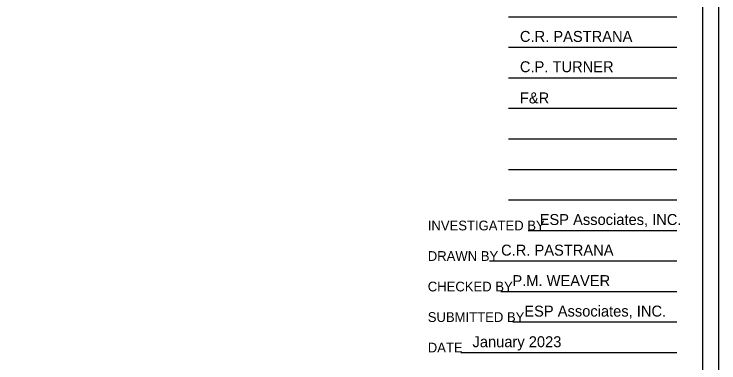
# Model space of a CAD drawing. Extents: x 265553 to 275568, y 168312 to 173522.
# Drawn here: x 267932 to 268472, y 172522 to 172789 of the extents above; entities that cross this region are included whole.
import ezdxf

# ---------------------------------------------------------------- set-up
doc = ezdxf.new("R2010")
doc.units = 0
doc.layers.add('Geotech Sheets and Borders Cell', color=7, linetype='Continuous')
doc.layers.add('Sheet Plot Border Inside CELL', color=7, linetype='Continuous')

msp = doc.modelspace()

# ---------------------------------------------------------------- linework, layer by layer
at = {"layer": 'Geotech Sheets and Borders Cell'}
for p, q in [((268310.32, 172787.01), (268439.27, 172787.01)), ((268310.32, 172763.61), (268439.27, 172763.61)), ((268310.32, 172740.21), (268439.27, 172740.21)), ((268310.32, 172716.81), (268439.27, 172716.81)), ((268310.32, 172693.41), (268439.27, 172693.41)), ((268310.32, 172670.01), (268439.27, 172670.01)), ((268310.32, 172646.61), (268439.27, 172646.61)), ((268325.43, 172623.21), (268439.27, 172623.21)), ((268295.9, 172599.81), (268439.27, 172599.81)), ((268304.56, 172576.41), (268439.27, 172576.41)), ((268313.67, 172553.01), (268439.27, 172553.01)), ((268274.01, 172529.61), (268439.27, 172529.61))]:
    msp.add_line(p, q, dxfattribs=at)
msp.add_lwpolyline([(266959.02, 173192.58), (268459.02, 173192.58), (268459.02, 172142.58), (266959.02, 172142.58)], close=True, dxfattribs=at)
at = {"layer": 'Sheet Plot Border Inside CELL'}
msp.add_lwpolyline([(266803.85, 172139.74), (268471.52, 172139.74), (268471.52, 173195.41), (266803.85, 173195.41)], close=True, dxfattribs=at)

# ---------------------------------------------------------------- texts
at = {"layer": 'Geotech Sheets and Borders Cell'}
for s, height, p in [('C.R. PASTRANA', 8.4, (268319.13, 172767.74)), ('C.P. TURNER', 8.4, (268319.13, 172744.49)), ('F&R', 8.4, (268319.13, 172720.58)), ('ESP Associates, INC.', 8.4, (268334.25, 172627.34)), ('INVESTIGATED BY', 7.4878, (268248.56, 172623.21)), ('C.R. PASTRANA', 8.4, (268304.71, 172603.88)), ('DRAWN BY', 7.488, (268248.56, 172599.81)), ('P.M. WEAVER', 8.4, (268313.38, 172580.5)), ('CHECKED BY', 7.488, (268248.56, 172576.41)), ('ESP Associates, INC.', 8.4, (268322.49, 172557.12)), ('SUBMITTED BY', 7.4878, (268248.56, 172553.01)), ('January 2023', 8.4, (268282.82, 172533.63)), ('DATE', 7.488, (268248.56, 172529.61))]:
    msp.add_text(s, height=height, dxfattribs=at).set_placement(p)

doc.saveas('drawing.dxf')
